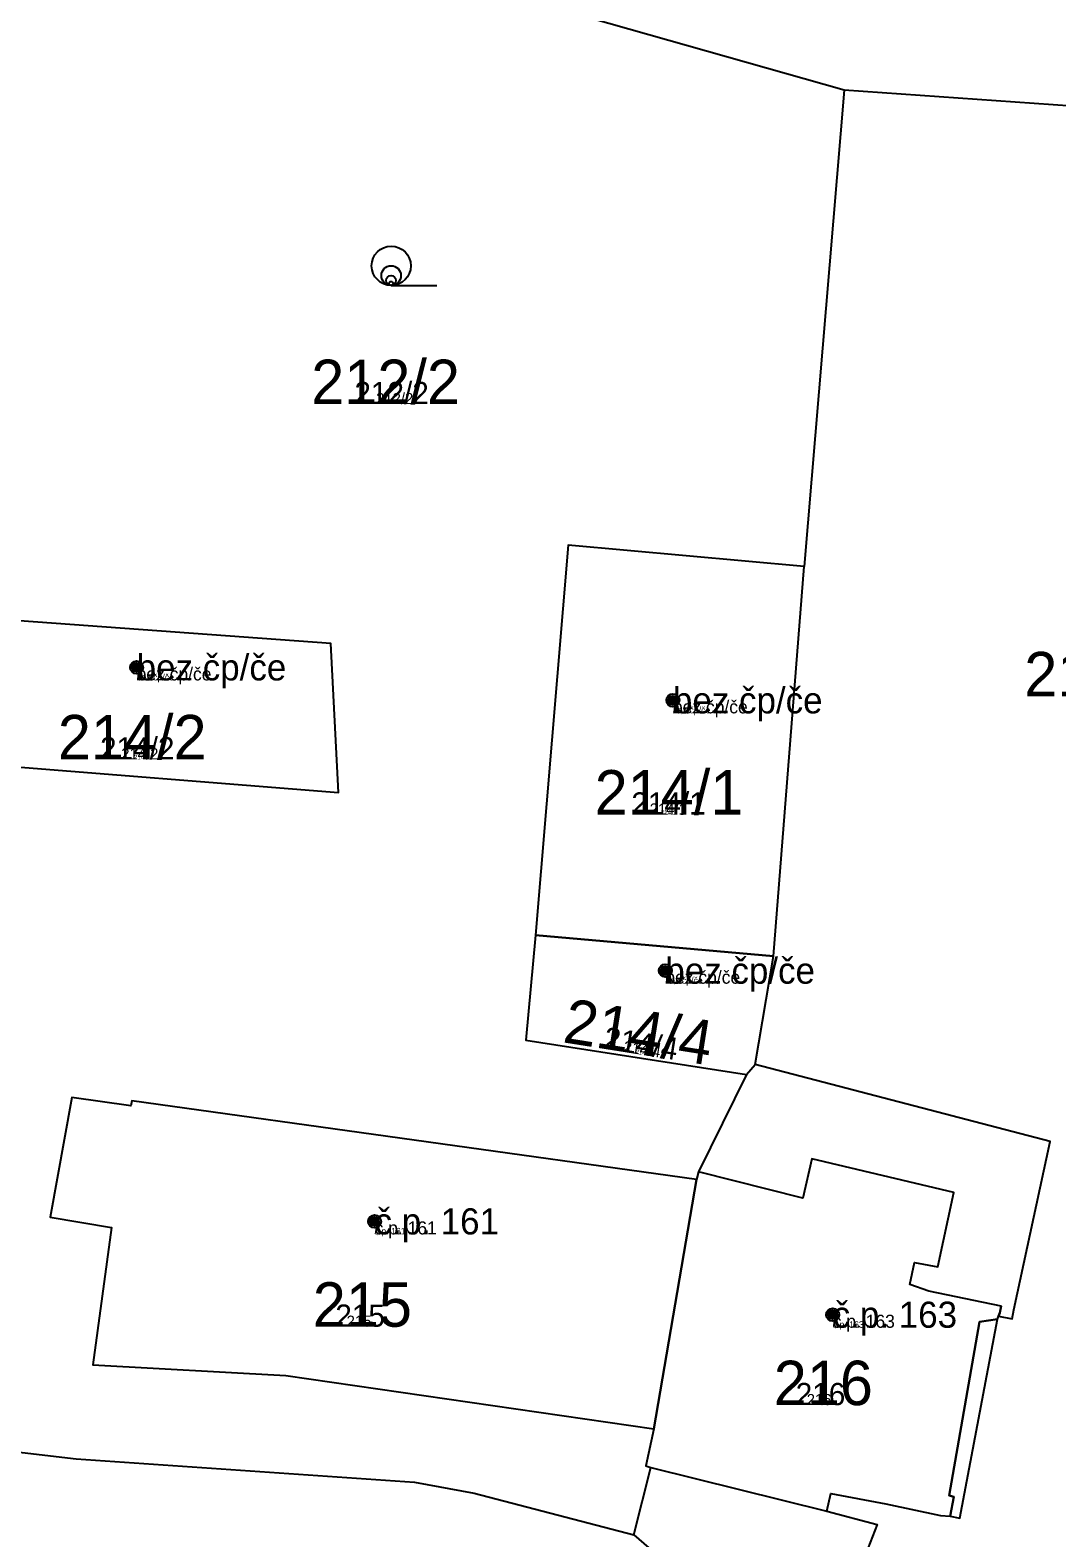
# Model space of a CAD drawing. Extents: x -744652 to -739090, y -980828 to -975855.
# Drawn here: x -742218 to -742178.7, y -978683.6 to -978626 of the extents above; entities that cross this region are included whole.
import ezdxf

# ---------------------------------------------------------------- set-up
doc = ezdxf.new("R2010")
doc.units = 0
for name, color, linetype in [('KAT_02_hranice parcel', 7, 'Continuous'), ('KAT_03_1000_st čísla parcelní', 7, 'Continuous'), ('KAT_03_1000_čísla parcelní', 7, 'Continuous'), ('KAT_03_1000_čísla popisná', 7, 'Continuous'), ('KAT_03_100_st čísla parcelní', 7, 'Continuous'), ('KAT_03_100_čísla parcelní', 7, 'Continuous'), ('KAT_03_100_čísla popisná', 7, 'Continuous'), ('KAT_03_250_st čísla parcelní', 7, 'Continuous'), ('KAT_03_250_čísla parcelní', 7, 'Continuous'), ('KAT_03_250_čísla popisná', 7, 'Continuous'), ('KAT_03_500_st čísla parcelní', 7, 'Continuous'), ('KAT_03_500_čísla parcelní', 7, 'Continuous'), ('KAT_03_500_čísla popisná', 7, 'Continuous'), ('KAT_04_vnitřní kresba', 7, 'Continuous'), ('KAT_05_1000_značky kultur', 7, 'Continuous'), ('KAT_05_100_značky kultur', 7, 'Continuous'), ('KAT_05_250_značky kultur', 7, 'Continuous'), ('KAT_05_500_značky kultur', 7, 'Continuous'), ('KAT_07_1000_značky budov', 7, 'Continuous'), ('KAT_07_100_značky budov', 7, 'Continuous'), ('KAT_07_500_značky budov', 7, 'Continuous'), ('KAT_14_plocha_budovy', 7, 'Continuous')]:
    doc.layers.add(name, color=color, linetype=linetype)

msp = doc.modelspace()

# ---------------------------------------------------------------- linework, layer by layer
at = {"layer": 'KAT_02_hranice parcel'}
for p, q in [((-742186.86, -978628.26), (-742188.39, -978646.48)), ((-742159.17, -978630.2), (-742186.86, -978628.26)), ((-742189.56, -978661.38), (-742188.39, -978646.48)), ((-742198.66, -978660.58), (-742189.56, -978661.38)), ((-742190.27, -978665.53), (-742189.56, -978661.38)), ((-742190.59, -978665.91), (-742190.27, -978665.53)), ((-742194.14, -978679.47), (-742192.51, -978669.93)), ((-742194.91, -978683.52), (-742194.25, -978680.94)), ((-742194.25, -978680.94), (-742187.52, -978682.61))]:
    msp.add_line(p, q, dxfattribs=at)
for points in [[(-742186.86, -978628.26), (-742199.59, -978624.64), (-742219.81, -978615.31)], [(-742188.39, -978646.48), (-742197.42, -978645.67), (-742198.66, -978660.58)], [(-742219.97, -978654.03), (-742206.2, -978655.13), (-742206.49, -978649.43), (-742221.74, -978648.32)], [(-742198.66, -978660.58), (-742199.03, -978664.6), (-742190.59, -978665.91)], [(-742187.52, -978682.61), (-742187.37, -978681.94), (-742185.27, -978682.33), (-742183.18, -978682.78), (-742182.81, -978682.81), (-742182.44, -978682.88), (-742181, -978675.27), (-742180.96, -978675.16), (-742180.43, -978675.26), (-742180.37, -978674.92), (-742178.98, -978668.47), (-742190.27, -978665.53)], [(-742190.59, -978665.91), (-742192.43, -978669.64), (-742192.51, -978669.93)], [(-742192.51, -978669.93), (-742214.1, -978666.92), (-742214.14, -978667.11), (-742216.4, -978666.79), (-742217.23, -978671.37), (-742214.88, -978671.76), (-742215.59, -978677.02), (-742208.21, -978677.43), (-742194.14, -978679.47)], [(-742194.14, -978679.47), (-742194.44, -978680.88), (-742194.25, -978680.94)], [(-742220.04, -978680.17), (-742216.23, -978680.61), (-742203.29, -978681.51), (-742201.01, -978681.93), (-742194.91, -978683.52)], [(-742187.52, -978682.61), (-742185.6, -978683.13), (-742186.05, -978684.27), (-742187.42, -978688.65), (-742183.5, -978692.11), (-742179.03, -978694.85)], [(-742194.91, -978683.52), (-742179.64, -978696.75), (-742156.06, -978711.55)]]:
    msp.add_lwpolyline(points, dxfattribs=at)
at = {"layer": 'KAT_03_1000_čísla popisná'}
for centre in [(-742213.92, -978650.34), (-742213.92, -978650.34), (-742193.41, -978651.6), (-742193.41, -978651.6), (-742193.7, -978661.94), (-742193.7, -978661.94), (-742204.82, -978671.53), (-742204.82, -978671.53), (-742187.3, -978675.1), (-742187.3, -978675.1)]:
    msp.add_circle(centre, 0.25, dxfattribs=at)
at = {"layer": 'KAT_03_100_čísla popisná'}
for centre in [(-742213.92, -978650.34), (-742213.92, -978650.34), (-742193.41, -978651.6), (-742193.41, -978651.6), (-742193.7, -978661.94), (-742193.7, -978661.94), (-742204.82, -978671.53), (-742204.82, -978671.53), (-742187.3, -978675.1), (-742187.3, -978675.1)]:
    msp.add_circle(centre, 0.025, dxfattribs=at)
at = {"layer": 'KAT_03_250_čísla popisná'}
for centre in [(-742213.92, -978650.34), (-742213.92, -978650.34), (-742193.41, -978651.6), (-742193.41, -978651.6), (-742193.7, -978661.94), (-742193.7, -978661.94), (-742204.82, -978671.53), (-742204.82, -978671.53), (-742187.3, -978675.1), (-742187.3, -978675.1)]:
    msp.add_circle(centre, 0.0625, dxfattribs=at)
at = {"layer": 'KAT_03_500_čísla popisná'}
for centre in [(-742213.92, -978650.34), (-742213.92, -978650.34), (-742193.41, -978651.6), (-742193.41, -978651.6), (-742193.7, -978661.94), (-742193.7, -978661.94), (-742204.82, -978671.53), (-742204.82, -978671.53), (-742187.3, -978675.1), (-742187.3, -978675.1)]:
    msp.add_circle(centre, 0.125, dxfattribs=at)
at = {"layer": 'KAT_04_vnitřní kresba'}
for p, q in [((-742188.1, -978669.14), (-742188.44, -978670.64)), ((-742182.67, -978670.43), (-742188.1, -978669.14)), ((-742188.44, -978670.64), (-742192.43, -978669.64)), ((-742183.28, -978673.27), (-742182.67, -978670.43)), ((-742184.35, -978673.95), (-742184.17, -978673.1)), ((-742184.17, -978673.1), (-742183.28, -978673.27)), ((-742183.62, -978674.2), (-742184.35, -978673.95)), ((-742180.86, -978674.77), (-742183.62, -978674.2)), ((-742180.86, -978674.77), (-742180.91, -978675.03)), ((-742181.68, -978675.37), (-742182.85, -978682.01)), ((-742181, -978675.27), (-742181.68, -978675.37)), ((-742180.91, -978675.03), (-742180.96, -978675.16)), ((-742182.85, -978682.01), (-742182.66, -978682.06)), ((-742182.66, -978682.06), (-742182.81, -978682.81))]:
    msp.add_line(p, q, dxfattribs=at)
at = {"layer": 'KAT_05_1000_značky kultur'}
msp.add_line((-742204.183, -978635.73), (-742202.433, -978635.73), dxfattribs=at)
msp.add_circle((-742204.183, -978634.98), 0.75, dxfattribs=at)
at = {"layer": 'KAT_05_100_značky kultur'}
msp.add_line((-742204.189, -978635.73), (-742204.014, -978635.73), dxfattribs=at)
msp.add_circle((-742204.189, -978635.655), 0.075, dxfattribs=at)
at = {"layer": 'KAT_05_250_značky kultur'}
msp.add_line((-742204.188, -978635.73), (-742203.751, -978635.73), dxfattribs=at)
msp.add_circle((-742204.188, -978635.542), 0.187, dxfattribs=at)
at = {"layer": 'KAT_05_500_značky kultur'}
msp.add_line((-742204.187, -978635.73), (-742203.312, -978635.73), dxfattribs=at)
msp.add_circle((-742204.186, -978635.355), 0.375, dxfattribs=at)
at = {"layer": 'KAT_07_1000_značky budov'}
for centre in [(-742213.927, -978650.339), (-742193.417, -978651.599), (-742193.707, -978661.939), (-742204.827, -978671.529), (-742187.307, -978675.099)]:
    msp.add_circle(centre, 0.175, dxfattribs=at)
at = {"layer": 'KAT_07_100_značky budov'}
for centre in [(-742213.921, -978650.34), (-742193.411, -978651.6), (-742193.701, -978661.94), (-742204.821, -978671.53), (-742187.301, -978675.1)]:
    msp.add_circle(centre, 0.0175, dxfattribs=at)
at = {"layer": 'KAT_07_500_značky budov'}
for centre, radius in [((-742213.923, -978650.34), 0.0875), ((-742213.922, -978650.34), 0.0438), ((-742193.413, -978651.6), 0.0875), ((-742193.412, -978651.6), 0.0438), ((-742193.703, -978661.94), 0.0875), ((-742193.702, -978661.94), 0.0438), ((-742204.823, -978671.53), 0.0875), ((-742204.822, -978671.53), 0.0438), ((-742187.303, -978675.1), 0.0875), ((-742187.302, -978675.1), 0.0438)]:
    msp.add_circle(centre, radius, dxfattribs=at)
at = {"layer": 'KAT_14_plocha_budovy'}
for points in [[(-742197.42, -978645.67), (-742198.66, -978660.58), (-742189.56, -978661.38), (-742188.39, -978646.48)], [(-742221.74, -978648.32), (-742219.97, -978654.03), (-742206.2, -978655.13), (-742206.49, -978649.43)], [(-742199.03, -978664.6), (-742190.59, -978665.91), (-742190.27, -978665.53), (-742189.56, -978661.38), (-742198.66, -978660.58)], [(-742214.1, -978666.92), (-742214.14, -978667.11), (-742216.4, -978666.79), (-742217.23, -978671.37), (-742214.88, -978671.76), (-742215.59, -978677.02), (-742208.21, -978677.43), (-742194.14, -978679.47), (-742192.51, -978669.93)], [(-742182.81, -978682.81), (-742182.66, -978682.06), (-742182.85, -978682.01), (-742181.68, -978675.37), (-742181, -978675.27), (-742180.96, -978675.16), (-742180.91, -978675.03), (-742180.86, -978674.77), (-742183.62, -978674.2), (-742184.35, -978673.95), (-742184.17, -978673.1), (-742183.28, -978673.27), (-742182.67, -978670.43), (-742188.1, -978669.14), (-742188.44, -978670.64), (-742192.43, -978669.64), (-742192.51, -978669.93), (-742194.14, -978679.47), (-742194.44, -978680.88), (-742194.25, -978680.94), (-742187.52, -978682.61), (-742187.37, -978681.94), (-742185.27, -978682.33), (-742183.18, -978682.78)]]:
    msp.add_lwpolyline(points, close=True, dxfattribs=at)

# ---------------------------------------------------------------- texts
at = {"layer": 'KAT_03_1000_st čísla parcelní'}
for s, p in [('214/2', (-742216.933, -978653.86)), ('214/1', (-742196.403, -978655.97)), ('215', (-742207.184, -978675.56)), ('216', (-742189.554, -978678.56))]:
    msp.add_text(s, height=1.7, dxfattribs=at).set_placement(p)
msp.add_text('214/4', height=1.7, rotation=351, dxfattribs=at).set_placement((-742197.662, -978664.675))
at = {"layer": 'KAT_03_1000_čísla parcelní'}
for s, p in [('212/2', (-742207.243, -978640.27)), ('212/1', (-742179.973, -978651.45))]:
    msp.add_text(s, height=1.7, dxfattribs=at).set_placement(p)
at = {"layer": 'KAT_03_1000_čísla popisná'}
for s, height, p in [('bez čp/če', 1, (-742213.92, -978650.84)), ('bez čp/če', 1, (-742193.41, -978652.1)), ('214/2', 0.017, (-742213.733, -978653.86)), ('214/1', 0.017, (-742193.62, -978655.97)), ('bez čp/če', 1, (-742193.7, -978662.44)), ('č.p. 161', 1, (-742204.82, -978672.03)), ('č.p. 163', 1, (-742187.3, -978675.6)), ('215', 0.017, (-742205.475, -978675.56)), ('216', 0.017, (-742187.891, -978678.56))]:
    msp.add_text(s, height=height, dxfattribs=at).set_placement(p)
msp.add_text('214/4', height=0.017, rotation=351, dxfattribs=at).set_placement((-742194.573, -978665.164))
at = {"layer": 'KAT_03_100_st čísla parcelní'}
for s, p in [('214/2', (-742214.024, -978653.86)), ('214/1', (-742193.873, -978655.97)), ('215', (-742205.63, -978675.56)), ('216', (-742188.042, -978678.56))]:
    msp.add_text(s, height=0.17, dxfattribs=at).set_placement(p)
msp.add_text('214/4', height=0.17, rotation=351, dxfattribs=at).set_placement((-742194.854, -978665.12))
at = {"layer": 'KAT_03_100_čísla parcelní'}
msp.add_text('212/2', height=0.17, dxfattribs=at).set_placement((-742204.268, -978640.27))
at = {"layer": 'KAT_03_100_čísla popisná'}
for s, height, p in [('bez čp/če', 0.1, (-742213.92, -978650.84)), ('bez čp/če', 0.1, (-742193.41, -978652.1)), ('214/2', 0.0017, (-742213.704, -978653.86)), ('214/1', 0.0017, (-742193.595, -978655.97)), ('bez čp/če', 0.1, (-742193.7, -978662.44)), ('č.p. 161', 0.1, (-742204.82, -978672.03)), ('215', 0.0017, (-742205.459, -978675.56)), ('č.p. 163', 0.1, (-742187.3, -978675.6)), ('216', 0.0017, (-742187.876, -978678.56))]:
    msp.add_text(s, height=height, dxfattribs=at).set_placement(p)
msp.add_text('214/4', height=0.0017, rotation=351, dxfattribs=at).set_placement((-742194.545, -978665.169))
at = {"layer": 'KAT_03_250_st čísla parcelní'}
for s, p in [('214/2', (-742214.509, -978653.86)), ('214/1', (-742194.295, -978655.97)), ('215', (-742205.889, -978675.56)), ('216', (-742188.294, -978678.56))]:
    msp.add_text(s, height=0.425, dxfattribs=at).set_placement(p)
msp.add_text('214/4', height=0.425, rotation=351, dxfattribs=at).set_placement((-742195.322, -978665.046))
at = {"layer": 'KAT_03_250_čísla parcelní'}
msp.add_text('212/2', height=0.425, dxfattribs=at).set_placement((-742204.763, -978640.27))
at = {"layer": 'KAT_03_250_čísla popisná'}
for s, height, p in [('bez čp/če', 0.25, (-742213.92, -978650.84)), ('bez čp/če', 0.25, (-742193.41, -978652.1)), ('214/2', 0.00425, (-742213.709, -978653.86)), ('214/1', 0.00425, (-742193.599, -978655.97)), ('bez čp/če', 0.25, (-742193.7, -978662.44)), ('č.p. 161', 0.25, (-742204.82, -978672.03)), ('215', 0.00425, (-742205.462, -978675.56)), ('č.p. 163', 0.25, (-742187.3, -978675.6)), ('216', 0.00425, (-742187.878, -978678.56))]:
    msp.add_text(s, height=height, dxfattribs=at).set_placement(p)
msp.add_text('214/4', height=0.00425, rotation=351, dxfattribs=at).set_placement((-742194.55, -978665.168))
at = {"layer": 'KAT_03_500_st čísla parcelní'}
for s, p in [('214/2', (-742215.317, -978653.86)), ('214/1', (-742194.998, -978655.97)), ('215', (-742206.321, -978675.56)), ('216', (-742188.714, -978678.56))]:
    msp.add_text(s, height=0.85, dxfattribs=at).set_placement(p)
msp.add_text('214/4', height=0.85, rotation=351, dxfattribs=at).set_placement((-742196.102, -978664.922))
at = {"layer": 'KAT_03_500_čísla parcelní'}
msp.add_text('212/2', height=0.85, dxfattribs=at).set_placement((-742205.59, -978640.27))
at = {"layer": 'KAT_03_500_čísla popisná'}
for s, height, p in [('bez čp/če', 0.5, (-742213.92, -978650.84)), ('bez čp/če', 0.5, (-742193.41, -978652.1)), ('214/2', 0.0085, (-742213.717, -978653.86)), ('214/1', 0.0085, (-742193.606, -978655.97)), ('bez čp/če', 0.5, (-742193.7, -978662.44)), ('č.p. 161', 0.5, (-742204.82, -978672.03)), ('215', 0.0085, (-742205.466, -978675.56)), ('č.p. 163', 0.5, (-742187.3, -978675.6)), ('216', 0.0085, (-742187.883, -978678.56))]:
    msp.add_text(s, height=height, dxfattribs=at).set_placement(p)
msp.add_text('214/4', height=0.0085, rotation=351, dxfattribs=at).set_placement((-742194.558, -978665.167))

doc.saveas('drawing.dxf')
